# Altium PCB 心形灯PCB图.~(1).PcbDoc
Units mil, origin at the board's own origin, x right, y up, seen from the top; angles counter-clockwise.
Board outline 5315 x 3937.01 mil, 2 copper layers (Top Layer, Bottom Layer); 75 components, 69 nets, 206 pads, 0 vias.
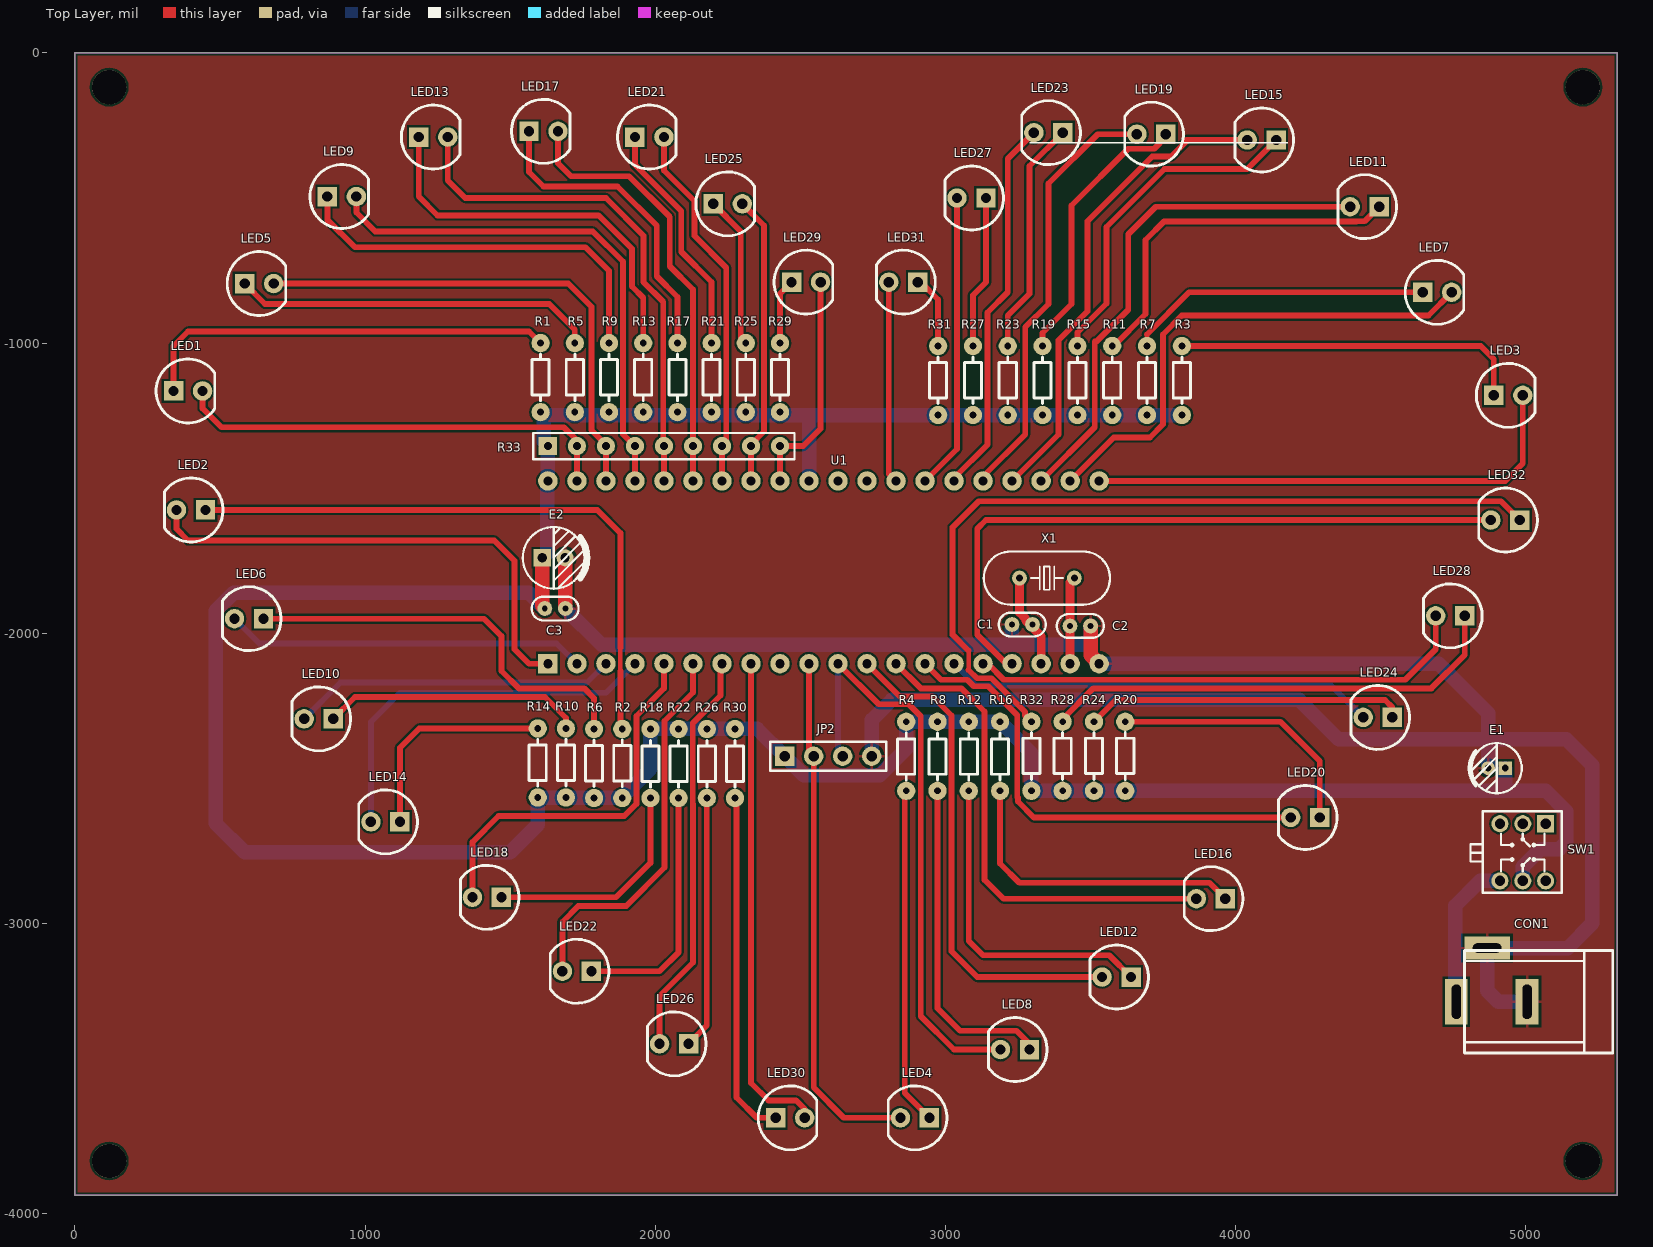
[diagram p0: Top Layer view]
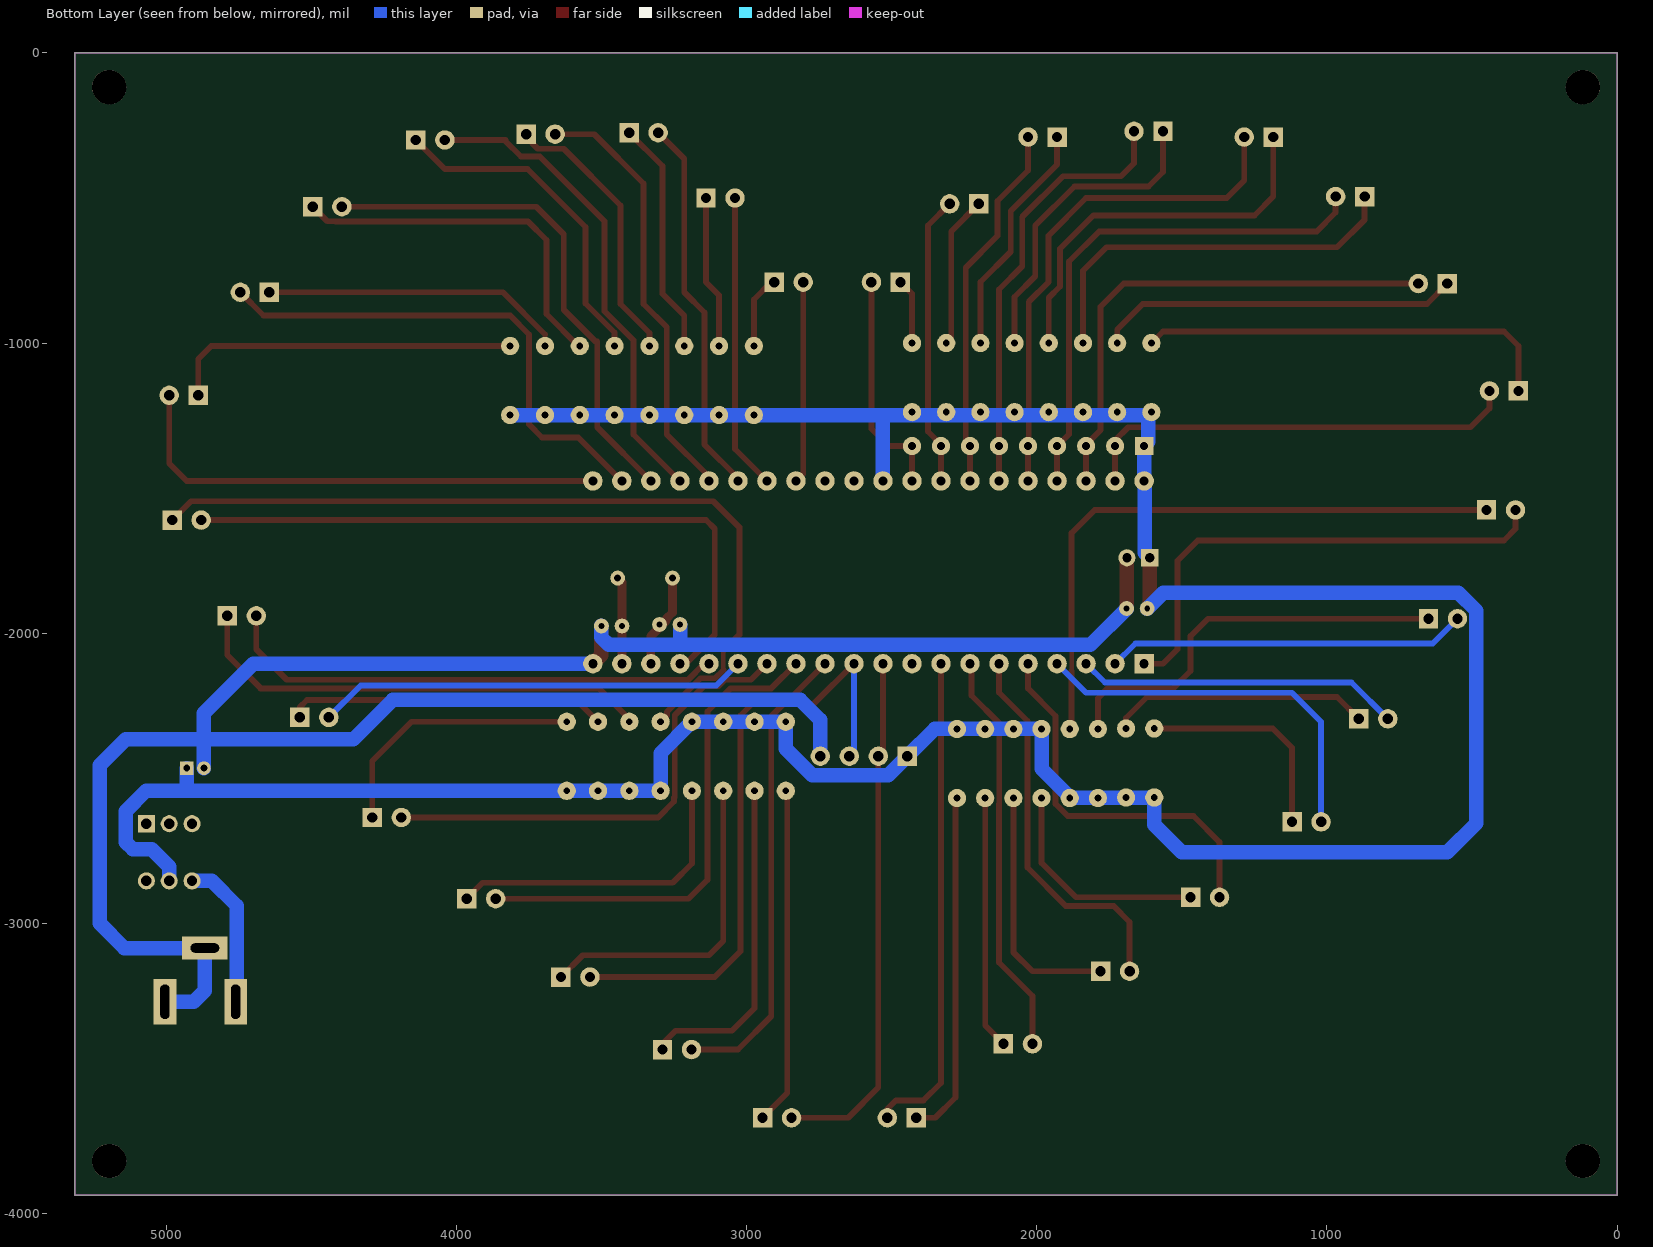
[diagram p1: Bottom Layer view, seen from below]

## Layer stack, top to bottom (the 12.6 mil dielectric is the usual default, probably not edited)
Top Solder: solder mask 0.4, Solder Resist, Dk 3.5
Top Layer: signal copper 1.4
Dielectric 1: dielectric 12.6, FR-4, Dk 4.8
Bottom Layer: signal copper 1.4
Bottom Solder: solder mask 0.4, Solder Resist, Dk 3.5

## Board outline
0,-3937.01 0,0 5315,0 5315,-3937.01

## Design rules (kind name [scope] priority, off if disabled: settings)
Clearance [All] p1: gap=7
PolygonConnect [All] p1: connectstyle=Relief reliefconductorwidth=10 reliefentries=4 polygonreliefangle="90 Angle" airgapwidth=10
RoutingVias [All] p1: holewidth=28 width=50 viastyle="Through Hole" minholewidth=28 minwidth=50 maxholewidth=28 maxwidth=50
SolderMaskExpansion [All] p1: expansion=4
Width Width-POWER [InNetClass('POWER')] p1: maxlimit=60 minlimit=50 preferedwidth=50
Width Width_1 [All] p2: maxlimit=30 minlimit=10 preferedwidth=20
30 further rules are at their usual default settings.

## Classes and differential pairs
net class POWER: +5V GND VCC

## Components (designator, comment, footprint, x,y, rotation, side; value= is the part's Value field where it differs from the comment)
C1 "104" "CC 1.8*3.6" 3265,-1970 r0 top
C2 "104" "CC 1.8*3.6" 3465,-1975 r180 top
C3 "104" "CC 1.8*3.6" 1655,-1915 r180 top
CON1 "3.5*1.3" DC-005 5005,-3270 r0 top
E1 "10uF/16V" "CAP 1.5*4*8" 4900,-2465 r180 top
E2 "100uF/16V" "CAP 2.0*5*11" 1650,-1740 r0 top
JP2 "TTL下载" HDR2.54-LI-4P 2596.06,-2423.94 r0 top
LED1 "红色" "LED 5MM-W" 390,-1165 r0 top
LED2 "红色" "LED 5MM-W" 400,-1575 r180 top
LED3 "红色" "LED 5MM-W" 4940,-1180 r0 top
LED4 "红色" "LED 5MM-W" 2895,-3670 r180 top
LED5 "红色" "LED 5MM-W" 635,-795 r0 top
LED6 "红色" "LED 5MM-W" 600,-1950 r180 top
LED7 "红色" "LED 5MM-W" 4695,-825 r0 top
LED8 "红色" "LED 5MM-W" 3240,-3435 r180 top
LED9 "红色" "LED 5MM-W" 920,-495 r0 top
LED10 "红色" "LED 5MM-W" 840,-2295 r180 top
LED11 "红色" "LED 5MM-W" 4445,-530 r180 top
LED12 "红色" "LED 5MM-W" 3590,-3185 r180 top
LED13 "红色" "LED 5MM-W" 1235,-290 r0 top
LED14 "红色" "LED 5MM-W" 1070,-2650 r180 top
LED15 "红色" "LED 5MM-W" 4090,-300 r180 top
LED16 "红色" "LED 5MM-W" 3915,-2915 r180 top
LED17 "红色" "LED 5MM-W" 1615,-270 r0 top
LED18 "红色" "LED 5MM-W" 1420,-2910 r180 top
LED19 "红色" "LED 5MM-W" 3710,-280 r180 top
LED20 "红色" "LED 5MM-W" 4240,-2635 r180 top
LED21 "红色" "LED 5MM-W" 1980,-290 r0 top
LED22 "红色" "LED 5MM-W" 1730,-3165 r180 top
LED23 "红色" "LED 5MM-W" 3355,-275 r180 top
LED24 "红色" "LED 5MM-W" 4490,-2290 r180 top
LED25 "红色" "LED 5MM-W" 2250,-520 r0 top
LED26 "红色" "LED 5MM-W" 2065,-3415 r180 top
LED27 "红色" "LED 5MM-W" 3090,-500 r180 top
LED28 "红色" "LED 5MM-W" 4740,-1940 r180 top
LED29 "红色" "LED 5MM-W" 2520,-790 r0 top
LED30 "红色" "LED 5MM-W" 2465,-3670 r0 top
LED31 "红色" "LED 5MM-W" 2855,-790 r180 top
LED32 "红色" "LED 5MM-W" 4930,-1610 r180 top
R1 "1K" "RS 1/8W" 1605,-1120 r270 top
R2 "1K" "RS 1/8W" 1886.43,-2450 r270 top
R3 "1K" "RS 1/8W" 3815,-1130 r270 top
R4 "1K" "RS 1/8W" 2865,-2423.11 r90 top
R5 "1K" "RS 1/8W" 1722.86,-1120 r270 top
R6 "1K" "RS 1/8W" 1789.29,-2450 r270 top
R7 "1K" "RS 1/8W" 3695,-1130 r270 top
R8 "1K" "RS 1/8W" 2972.86,-2423.11 r90 top
R9 "1K" "RS 1/8W" 1840.71,-1120 r270 top
R10 "1K" "RS 1/8W" 1692.14,-2448.11 r270 top
R11 "1K" "RS 1/8W" 3575,-1130 r270 top
R12 "1K" "RS 1/8W" 3080.71,-2423.11 r90 top
R13 "1K" "RS 1/8W" 1958.57,-1120 r270 top
R14 "1K" "RS 1/8W" 1595,-2448.11 r270 top
R15 "1K" "RS 1/8W" 3455,-1130 r270 top
R16 "1K" "RS 1/8W" 3188.57,-2423.11 r90 top
R17 "1K" "RS 1/8W" 2076.43,-1120 r270 top
R18 "1K" "RS 1/8W" 1983.57,-2448.11 r90 top
R19 "1K" "RS 1/8W" 3335,-1130 r270 top
R20 "1K" "RS 1/8W" 3620,-2425 r270 top
R21 "1K" "RS 1/8W" 2194.28,-1120 r270 top
R22 "1K" "RS 1/8W" 2080.71,-2448.11 r90 top
R23 "1K" "RS 1/8W" 3215,-1130 r270 top
R24 "1K" "RS 1/8W" 3512.14,-2425 r270 top
R25 "1K" "RS 1/8W" 2312.14,-1120 r270 top
R26 "1K" "RS 1/8W" 2177.86,-2448.11 r90 top
R27 "1K" "RS 1/8W" 3095,-1130 r270 top
R28 "1K" "RS 1/8W" 3404.29,-2425 r270 top
R29 "1K" "RS 1/8W" 2430,-1120 r270 top
R30 "1K" "RS 1/8W" 2275,-2448.11 r90 top
R31 "1K" "RS 1/8W" 2975,-1130 r270 top
R32 "1K" "RS 1/8W" 3296.43,-2425 r270 top
R33 "103" "R SIP9-2.54" 2030,-1355 r0 top
SW1 "KET 7X7" "KFT DIP-7X7" 4990,-2755 r180 top
U1 "STC89C52RC" 单片机40 1630,-2105 r90 top
X1 "12MHz" "OSC HC-49U" 3350,-1810 r180 top

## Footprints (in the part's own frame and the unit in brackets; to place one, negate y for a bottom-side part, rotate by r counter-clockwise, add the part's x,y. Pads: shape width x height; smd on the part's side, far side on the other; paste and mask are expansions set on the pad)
"CAP 1.5*4*8" [mm] "脚距1.5mm直径4mm高度8mm"
  rect 1.2x1.2 hole 0.6: 1(-0.75,0)
  round 1.2 hole 0.6: 2(0.75,0)
  silkscreen extent -2.2,-2.2 2.41,2.2, body extent -2,-2 2.02,2, height 8.04
"CAP 2.0*5*11" [mm] "脚距2mm直径5mm高度11mm"
  rect 1.5x1.5 hole 0.8: 1(-1,0)
  round 1.5 hole 0.8: 2(1,0)
  silkscreen extent -2.7,-2.7 2.96,2.7, body extent -2.5,-2.5 2.51,2.5, height 11.04
"CC 1.8*3.6" [mm] "脚距1.8mm直径3.6mm"
  round 1.3 hole 0.5: 1(-0.9,0) 2(0.9,0)
  silkscreen extent -2.05,-1.04 2.05,1.04, body extent -1.8,-0.8 1.8,0.8, height 3.6
DC-005 [mm] "5.5*2.1mm，DC30V,2.5A"
  rect 2x4 hole 0.8 slot 3 at 90 deg: 1(-6.2,0) 2(0,0)
  rect 4x2 hole 0.8 slot 2.5 at 0 deg: 3(-3.5,4.7)
  silkscreen extent -5.48,-4.5 7.5,4.5, body extent -6.55,-4.5 7.5,4.8, height 11.2
HDR2.54-LI-4P [mm] "排针，4脚"
  rect 1.7x1.7 hole 0.9: 1(-3.81,0)
  round 1.7 hole 0.9: 2(-1.27,0) 3(1.27,0) 4(3.81,0)
  silkscreen extent -5.08,-1.27 5.08,1.27, body extent -5.08,-1.27 5.08,1.27, height 8.5
"KFT DIP-7X7" [mm] "自锁开关，规格：7*7mm"
  rect 1.5x1.5 hole 0.9: 1(-2,-2.5)
  round 1.5 hole 0.9: 2(0,-2.5) 3(2,-2.5) 4(2,2.5) 5(0,2.5) 6(-2,2.5)
  silkscreen extent -3.42,-3.58 4.58,3.56, body extent -3.5,-3.5 3.5,3.5, height 11.2
"LED 5MM-W" [mm] "白色5mm直插LED"
  rect 1.7x1.7 hole 0.9: 1(-1.27,0)
  round 1.7 hole 0.9: 2(1.27,0)
  silkscreen extent -2.8,-2.8 2.33,2.8, body extent -2.85,-2.85 2.45,2.85, height 8.75
"OSC HC-49U" [mm]
  round 1.3 hole 0.6: 1(-2.4,0) 2(2.4,0)
  silkscreen extent -5.52,-2.32 5.52,2.33, body extent -5.53,-2.33 5.52,2.32, height 13.95
"R SIP9-2.54" [mm] "22.6mm*5mm*2.2mm(长*宽*厚)"
  rect 1.6x1.6 hole 0.7: 1(-10.16,0)
  round 1.6 hole 0.7: 2(-7.62,0) 3(-5.08,0) 4(-2.54,0) 5(0,0) 6(2.54,0) 7(5.08,0) 8(7.62,0) 9(10.16,0)
  silkscreen extent -11.43,-1.14 11.43,1.14, body extent -11.31,-0.96 11.31,0.96, height 5.2
"RS 1/8W" [mm] "直插色环电阻，脚距6mm，直径1.5mm"
  round 1.6 hole 0.6: 1(-3.048,0) 2(3,0)
  silkscreen extent -2.1,-0.75 2,0.75, body extent -3.22,-0.76 3.23,0.76, height 1.52
单片机40 [mm]
  rect 1.7x1.7 hole 0.8: 1(0,0)
  round 1.7 hole 0.8: 2(0,-2.54) 3(0,-5.08) 4(0,-7.62) 5(0,-10.16) 6(0,-12.7) 7(0,-15.24) 8(0,-17.78) 9(0,-20.32) 10(0,-22.86) 11(0,-25.4) 12(0,-27.94) 13(0,-30.48) 14(0,-33.02) 15(0,-35.56) 16(0,-38.1) 17(0,-40.64) 18(0,-43.18) 19(0,-45.72) 20(0,-48.26) 21(16,-48.26) 22(16,-45.72) 23(16,-43.18) 24(16,-40.64) 25(16,-38.1) 26(16,-35.56) 27(16,-33.02) 28(16,-30.48) 29(16,-27.94) 30(16,-25.4) 31(16,-22.86) 32(16,-20.32) 33(16,-17.78) 34(16,-15.24) 35(16,-12.7) 36(16,-10.16) 37(16,-7.62) 38(16,-5.08) 39(16,-2.54) 40(16,0)

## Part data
C1 C2 C3: library part C-CC, "直插瓷片电容"
CON1: library part P-DC, "低压电源接口"
E1 E2: library part C-CAP, "直插电解电容"
JP2: library part "Header 4", "4P接插件"
LED1 LED2 LED3 LED4 LED5 LED6 LED7 LED8 LED9 LED10 LED11 LED12 LED13 LED14 LED15 LED16 LED17 LED18 LED19 LED20 LED21 LED22 LED23 LED24 LED25 LED26 LED27 LED28 LED29 LED30 LED31 LED32: library part LED-5MM, "5mm插件LED"
R1 R2 R3 R4 R5 R6 R7 R8 R9 R10 R11 R12 R13 R14 R15 R16 R17 R18 R19 R20 R21 R22 R23 R24 R25 R26 R27 R28 R29 R30 R31 R32: library part R-CRR, "直插色环电阻"
R33: library part "R SIP9", "单列直插排阻"
SW1: "7*7自锁开关"
U1: "STC单片机"
X1: library part XTAL-2P, "2脚无源脚晶振"

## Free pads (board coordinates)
  round 118.11 hole 118.11 unplated: 0(118.11,-3818.9) 0(118.11,-118.11) 0(5196.89,-3818.9) 0(5196.89,-118.11)

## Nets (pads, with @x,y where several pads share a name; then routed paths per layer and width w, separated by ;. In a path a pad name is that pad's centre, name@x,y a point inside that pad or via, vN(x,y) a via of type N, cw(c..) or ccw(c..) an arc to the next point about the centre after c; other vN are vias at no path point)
+5V: CON1.1 SW1.4 | length 522.5
  Bottom Layer w50: CON1.1 4756.46,-3265.56 4756.46,-2940 4843.04,-2853.43 SW1.4
GND: C1.1 C2.1 C3.1 CON1.2 CON1.3 E1.2 E2.2 JP2.4 U1.20 | length 7871.8
  Top Layer w50: C3.1@1689.37,-1913.94 E2.2 ; C2.1 3500.43,-2075.43 U1.20
  Bottom Layer w50: C3.1 1814.97,-2039.54 3475.46,-2039.54 3500.43,-2014.57 C2.1 ; JP2.4 2746.06,-2298.94 2815,-2230 4220,-2230 4355,-2365 4870.47,-2365 ; 3229.57,-2039.1 C1.1 ; U1.20 4700,-2105 4870.47,-2275.47 4870.47,-2365 ; E1.2 4870.47,-2365 ; CON1.2 4905,-3270 4867.2,-3232.2 CON1.3 5145.04,-3084.96 5230,-3000 5230,-2455 5140,-2365 4870.47,-2365
NetC1_2: C1.2 U1.18 X1.2 | length 325.9
  Top Layer w30: X1.2 3255.51,-1928.64 3277.16,-1950.29 3277.16,-1957.16 3330,-2010 U1.18
NetC2_2: C2.2 U1.19 X1.1 | length 300.7
  Top Layer w30: U1.19@3429.57,-2104.57 C2.2 3429.57,-1824.92 X1.1
NetLED1_1: LED1.1 R1.1 | length 1457.3
  Top Layer w20: LED1.1 340,-1010 390,-960 1565,-960 R1.1
NetLED2_1: LED2.1 R2.1 | length 2140.8
  Top Layer w15: 1880,-2130 1880,-2050
  Top Layer w20: LED2.1 1800,-1575 1880,-1655 1880,-2050 ; 1880,-2130 1880,-2323.57 R2.1
NetLED3_1: LED3.1 R3.1 | length 1218.6
  Top Layer w20: R3.1 4845,-1010 4890,-1055 LED3.1
NetLED4_1: LED4.1 R4.1 | length 1164.2
  Top Layer w20: R4.1 2860,-2548.11 2860,-3585 LED4.1
NetLED5_1: LED5.1 R5.1 | length 1250.4
  Top Layer w20: LED5.1 655,-865 1635,-865 1722.86,-952.86 R5.1
NetLED6_1: LED6.1 R6.1 | length 1428.9
  Top Layer w20: LED6.1 1410,-1950 1470,-2010 1470,-2130 1530,-2190 1755,-2190 1789.29,-2224.29 R6.1
NetLED7_1: LED7.1 R7.1 | length 1010.1
  Top Layer w20: 3695,-970 3840,-825 LED7.1
NetLED8_1: LED8.1 R8.1 | length 1137.5
  Top Layer w20: R8.1 2972.86,-3292.86 3050,-3370 3245,-3370 3290,-3415 LED8.1
NetLED9_1: LED9.1 R9.1 | length 1372.8
  Top Layer w20: LED9.1 870,-575 965,-670 1760,-670 1840.71,-750.71 R9.1
NetLED10_1: LED10.1 R10.1 | length 899.1
  Top Layer w20: LED10.1 965,-2220 1620,-2220 1692.14,-2292.14 R10.1
NetLED11_1: LED11.1 R11.1 | length 1268.2
  Top Layer w20: R11.1 3580,-1010 3690,-900 3690,-645 3754.54,-580.46 4415.9,-580.46 4416.37,-580 4445,-580 LED11.1
NetLED12_1: LED12.1 R12.1 | length 1128.4
  Top Layer w20: R12.1 3080.71,-3060.71 3130,-3110 3565,-3110 LED12.1
NetLED13_1: LED13.1 R13.1 | length 1355.5
  Top Layer w20: LED13.1 1185,-495 1250,-560 1805,-560 1920,-675 1920,-805 1958.57,-843.57 R13.1
NetLED14_1: LED14.1 R14.1 | length 757.7
  Top Layer w20: LED14.1 1120,-2395 1186.89,-2328.11 R14.1
NetLED15_1: LED15.1 R15.1 | length 1160.7
  Top Layer w20: R15.1 3455,-963.18 3555,-863.18 3555,-600 3755,-400 4040,-400 LED15.1
NetLED16_1: LED16.1 R16.1 | length 1077.2
  Top Layer w20: R16.1 3188.57,-2793.57 3255,-2860 3910,-2860 LED16.1
NetLED17_1: LED17.1 R17.1 | length 1091.2
  Top Layer w20: LED17.1 1565,-410 1615,-460 1870,-460 2005,-595 2005,-770 2076.43,-841.43 R17.1
NetLED18_1: LED18.1 R18.1 | length 786
  Top Layer w20: LED18.1 1865,-2910 1983.57,-2791.43 R18.1
NetLED19_1: LED19.1 R19.1 | length 958.2
  Top Layer w20: R19.1 3335,-965 3435,-865 3435,-525.93 3630.46,-330.46 3680.9,-330.46 3681.37,-330 3720,-330 3760,-290 LED19.1
NetLED20_1: LED20.1 R20.1 | length 920.9
  Top Layer w20: R20.1 4155,-2305 4290,-2440 LED20.1
NetLED21_1: LED21.1 R21.1 | length 819.5
  Top Layer w20: LED21.1 1930,-385 2090,-545 2090,-685 2194.28,-789.28 R21.1
NetLED22_1: LED22.1 R22.1 | length 859.1
  Top Layer w20: LED22.1 2015,-3165 2080.71,-3099.29 R22.1
NetLED23_1: LED23.1 R23.1 | length 813.7
  Top Layer w20: R23.1 3215,-905 3290,-830 3290,-390 LED23.1
NetLED24_1: LED24.1 R24.1 | length 1069.3
  Top Layer w20: R24.1 3587.14,-2230 4515,-2230 4540,-2255
NetLED25_1: LED25.1 R25.1 | length 526.5
  Top Layer w20: LED25.1 2295,-615 2295,-982.86 R25.1
NetLED26_1: LED26.1 R26.1 | length 872.9
  Top Layer w20: LED26.1 2177.86,-3352.14 R26.1
NetLED27_1: LED27.1 R27.1 | length 528.6
  Top Layer w20: R27.1 3095,-835 3140,-790 LED27.1
NetLED28_1: LED28.1 R28.1 | length 1621.4
  Top Layer w20: R28.1 3404.29,-2295.71 3510,-2190 4675,-2190 4790,-2075 LED28.1
NetLED29_1: LED29.1 R29.1 | length 226.6
  Top Layer w20: R29.1 2430,-830 LED29.1
NetLED30_1: LED30.1 R30.1 | length 1198
  Top Layer w20: R30.1 2280,-2573.11 2280,-3600 2350,-3670 LED30.1
NetLED31_1: LED31.1 R31.1 | length 254.9
  Top Layer w20: LED31.1 2915,-790 2975,-850 R31.1
NetLED32_1: LED32.1 R32.1 | length 2830.7
  Top Layer w15: 3080,-2126.37 3080,-2060
  Top Layer w20: 3080,-2126.37 3109.1,-2155.46 3158.65,-2155.46 3274.93,-2271.75 3274.93,-2283.5 R32.1 ; 3080,-2060 3025,-2005 3025,-1635 3115,-1545 4915,-1545 LED32.1
P0_0: LED1.2 R33.2 U1.39 | length 1542.7
  Top Layer w20: LED1.2@445,-1160 LED1.2 440,-1225 505,-1290 1685,-1290 1730,-1335 R33.2 U1.39
P0_1: LED5.2 R33.3 U1.38 | length 1748.9
  Top Layer w20: LED5.2 1700,-795 1780,-875 1780,-1300 1830,-1350 R33.3 U1.38
P0_2: LED9.2 R33.4 U1.37 | length 1817.1
  Top Layer w20: LED9.2 970,-550 1035,-615 1785,-615 1889.21,-719.21 1889.21,-1314.21 R33.4 U1.37
P0_3: LED13.2 R33.5 U1.36 | length 1779
  Top Layer w20: LED13.2 1285,-440 1345,-500 1830,-500 1960,-630 1960,-790 2027.93,-857.93 2027.93,-1355 R33.5 U1.36
P0_4: LED17.2 R33.6 U1.35 | length 1514.8
  Top Layer w20: LED17.2 1665,-380 1710,-425 1910,-425 2050,-565 2050,-735 2130,-815 R33.6 U1.35
P0_5: LED21.2 R33.7 U1.34 | length 1280.3
  Top Layer w20: LED21.2 2030,-405 2135,-510 2135,-630 2245,-740 2245,-1340 R33.7 U1.34
P0_6: LED25.2 R33.8 U1.33 | length 1004.8
  Top Layer w20: LED25.2 2375,-595 2375,-1305 2330,-1350 R33.8 U1.33
P0_7: LED29.2 R33.9 U1.32 | length 789.9
  Top Layer w20: U1.32 R33.9 2510,-1355 2570,-1295 LED29.2
P1_0: LED2.2 U1.1 | length 1716.3
  Top Layer w20: LED2.2 350,-1640 390,-1680 1445,-1680 1515,-1750 1515,-2055 1565,-2105 U1.1
P1_1: LED6.2 U1.2 | length 1244.2
  Bottom Layer w20: LED6.2 635,-2035 1660,-2035 U1.2
P1_2: LED10.2 U1.3 | length 1118.7
  Bottom Layer w20: LED10.2 915,-2170 1765,-2170 U1.3
P1_3: LED14.2 U1.4 | length 1337.8
  Bottom Layer w20: LED14.2 1020,-2305 1120,-2205 1830,-2205 U1.4
P1_4: LED18.2 U1.5 | length 1332.1
  Top Layer w20: LED18.2 1370,-2720 1460,-2630 1893.12,-2630 1935.07,-2588.05 1935.07,-2284.99 2030,-2190.06 U1.5
P1_5: LED22.2 U1.6 | length 1343.1
  Top Layer w20: LED22.2 1680,-2995 1735,-2940 1900,-2940 2032.22,-2807.78 2032.22,-2302.13 2130,-2204.35 U1.6
P1_6: LED26.2 U1.7 | length 1399.6
  Top Layer w20: LED26.2 2015,-3250 2130,-3135 2130,-2588.84 2129.36,-2588.2 2129.36,-2309.91 2225,-2214.27 2225,-2110 U1.7
P1_7: LED30.2 U1.8 | length 1697.3
  Top Layer w20: U1.8 2330,-3550 2390,-3610 2485,-3610 2515,-3640 LED30.2
P2_0: LED3.2 U1.21 | length 1719.9
  Top Layer w20: U1.21 4929.92,-1475.08 4990,-1415 LED3.2
P2_1: LED7.2 U1.22 | length 1765.9
  Top Layer w20: U1.22 3580.08,-1325 3705,-1325 3750,-1280 3750,-970 3815,-905 4665,-905 LED7.2
P2_2: LED11.2 U1.23 | length 1781.6
  Top Layer w20: U1.23 3515,-1290.08 3515,-995 3520,-995 3630,-885 3630,-625 3725,-530 LED11.2
P2_3: LED15.2 U1.24 | length 1667.1
  Top Layer w20: U1.24 3390,-1315.08 3390,-990 3490,-890 3490,-580 3713,-357 3778,-357 3830.97,-304.03 ; 3830.97,-300 LED15.2
P2_4: LED19.2 U1.25 | length 1493.7
  Top Layer w20: U1.25 3130,-1460 3275,-1315 3275,-945 3355,-865 3355,-450 3525,-280 LED19.2
P2_5: LED23.2 U1.26 | length 1314
  Top Layer w20: U1.26 3030,-1465 3145,-1350 3145,-895 3215,-825 3215,-365 LED23.2
P2_6: LED27.2 U1.27 | length 1020.6
  Top Layer w20: U1.27 3040,-1365.08 LED27.2
P2_7: LED31.2 U1.28 | length 695.4
  Top Layer w20: LED31.2 2805,-1450.08 U1.28
P3_0: JP2.2 LED4.2 U1.10 | length 1809.7
  Top Layer w20: U1.10 2530,-2407.87 JP2.2 2546.06,-3566.06 2650,-3670 LED4.2
P3_1: JP2.3 LED8.2 U1.11 | length 2042
  Top Layer w20: U1.11 2770,-2245 2873.58,-2245 2915,-2286.42 2915,-3320 3030,-3435 LED8.2
  Bottom Layer w20: U1.11 2630,-2407.87 JP2.3
P3_2: LED12.2 U1.12 | length 1733.5
  Top Layer w20: U1.12 2843,-2218 2955.79,-2218 3021.35,-2283.56 3021.35,-3096.35 3110,-3185 LED12.2
P3_3: LED16.2 U1.13 | length 1710.3
  Top Layer w20: U1.13 2915,-2190 3055,-2190 3135,-2270 3135,-2850 3200,-2915 LED16.2
P3_4: LED20.2 U1.14 | length 1652.3
  Top Layer w20: U1.14 2985,-2160 3075.45,-2160 3097.91,-2182.46 3147.46,-2182.46 3247.93,-2282.93 3247.93,-2565.27 3250,-2567.33 3250,-2580 3305,-2635 LED20.2
P3_5: LED24.2 U1.15 | length 1486.6
  Bottom Layer w20: U1.15 3105,-2180 4330,-2180 LED24.2
P3_6: LED28.2 U1.16 | length 1741.3
  Top Layer w20: U1.16 3131,-2106 3147.37,-2106 3201.37,-2160 4585,-2160 4690,-2055 LED28.2
P3_7: LED32.2 U1.17 | length 2308.8
  Top Layer w20: U1.17 3210,-2105 3110,-2005 3110,-1640 3140,-1610 LED32.2
VCC: C3.2 E1.1 E2.1 JP2.1 R1.2 R2.2 R3.2 R4.2 R5.2 R6.2 R7.2 R8.2 R9.2 R10.2 R11.2 R12.2 R13.2 R14.2 R15.2 R16.2 R17.2 R18.2 R19.2 R20.2 R21.2 R22.2 R23.2 R24.2 R25.2 R26.2 R27.2 R28.2 R29.2 R30.2 R31.2 R32.2 R33.1 SW1.5 U1.31 U1.40 | length 10793
  Top Layer w50: C3.2@1610.63,-1906.06 E2.1
  Bottom Layer w50: R33.1@1615,-1340 1615,-1248.11 R31.2 R27.2 R23.2 R19.2 R15.2 R11.2 R7.2 R3.2 ; C3.2 1564.57,-1860 547.42,-1860 484.54,-1922.88 484.54,-2654.54 585,-2755 1500,-2755 1595,-2660 R14.2 R10.2 1884.54,-2566.22 1983.57,-2467.19 R18.2 R22.2 R26.2 R30.2 2352.13,-2330 JP2.1 2511.53,-2489.4 2773.18,-2489.4 2865,-2397.58 R4.2 R8.2 R12.2 R16.2 3296.43,-2412.86 R32.2 R28.2 R24.2 R20.2 5070,-2543.11 5140,-2613.11 5140,-2720 5115,-2745 5050,-2745 4990,-2805 SW1.5 ; E2.1@1619.57,-1731.06 1627.84,-1722.79 1627.84,-1477.24 U1.40 R33.1 ; U1.31 2530,-1253.11 ; 4929.53,-2532.64 E1.1
pads on no net: SW1.1 SW1.2 SW1.3 SW1.6 U1.9 U1.29 U1.30

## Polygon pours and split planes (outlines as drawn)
GND on Top Layer "Keep-Out Layer-No Net" (solid, remove dead copper, pour order 0): 0,0 5315,0 5315,-3937.01 5302.01,-3950 5,-3950 5,-5 0,0

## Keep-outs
Keep-Out Layer:
  the board outline again, w5

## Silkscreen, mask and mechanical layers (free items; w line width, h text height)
Top Overlay:
  lines w5: 3290,-310 4180,-310

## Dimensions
0,0 to 0,-3937.01 on Keep-Out Layer
0,0 to 5315,0 on Keep-Out Layer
